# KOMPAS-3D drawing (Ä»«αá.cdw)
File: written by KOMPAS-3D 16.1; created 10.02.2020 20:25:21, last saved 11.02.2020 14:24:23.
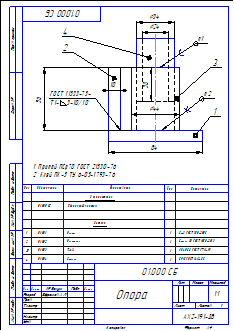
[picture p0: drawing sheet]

Sheet 1: A4, portrait

Title block, sheet 1: name: Опора; designation: 01.000 СБ; scale: 1:1; sheets: 1; organisation: АХ2-191-ДБ; sheet format: A4; stored path: D:\ЗАДАЧИ\Начертательная геометрия и инженерная графика. 4 задания Р\Задание 4\Опора.cdw; drawn by: Ефремов А.Л.

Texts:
  Пользователь Windows
  romans
  Детали
  Сборочный чертеж
  Документация
  Кол.
  Поз.
  Плита
  Ст.3 ГОСТ 380-2005
  Пластина
  Сталь 20 ГОСТ 1050-2013
  Труба
  ЛЦ4О СД ГОСТ 17711-93
  Стакан
  СЧ15 ГОСТ 1412-85
  ГОСТ 11533-75-
  Припой ПСр70 ГОСТ 21530-76.
  Клей ПК-5 ТУ 6-05-1793-76.
Dimensions and other numbers on the sheet: 01.000 СБ; 1; 01.001; 2; 01.002; 3; 01.003; 4; 01.004; 84; 10; 44; 34; 24; 30; 56; 1:1; 01.000 СБ-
